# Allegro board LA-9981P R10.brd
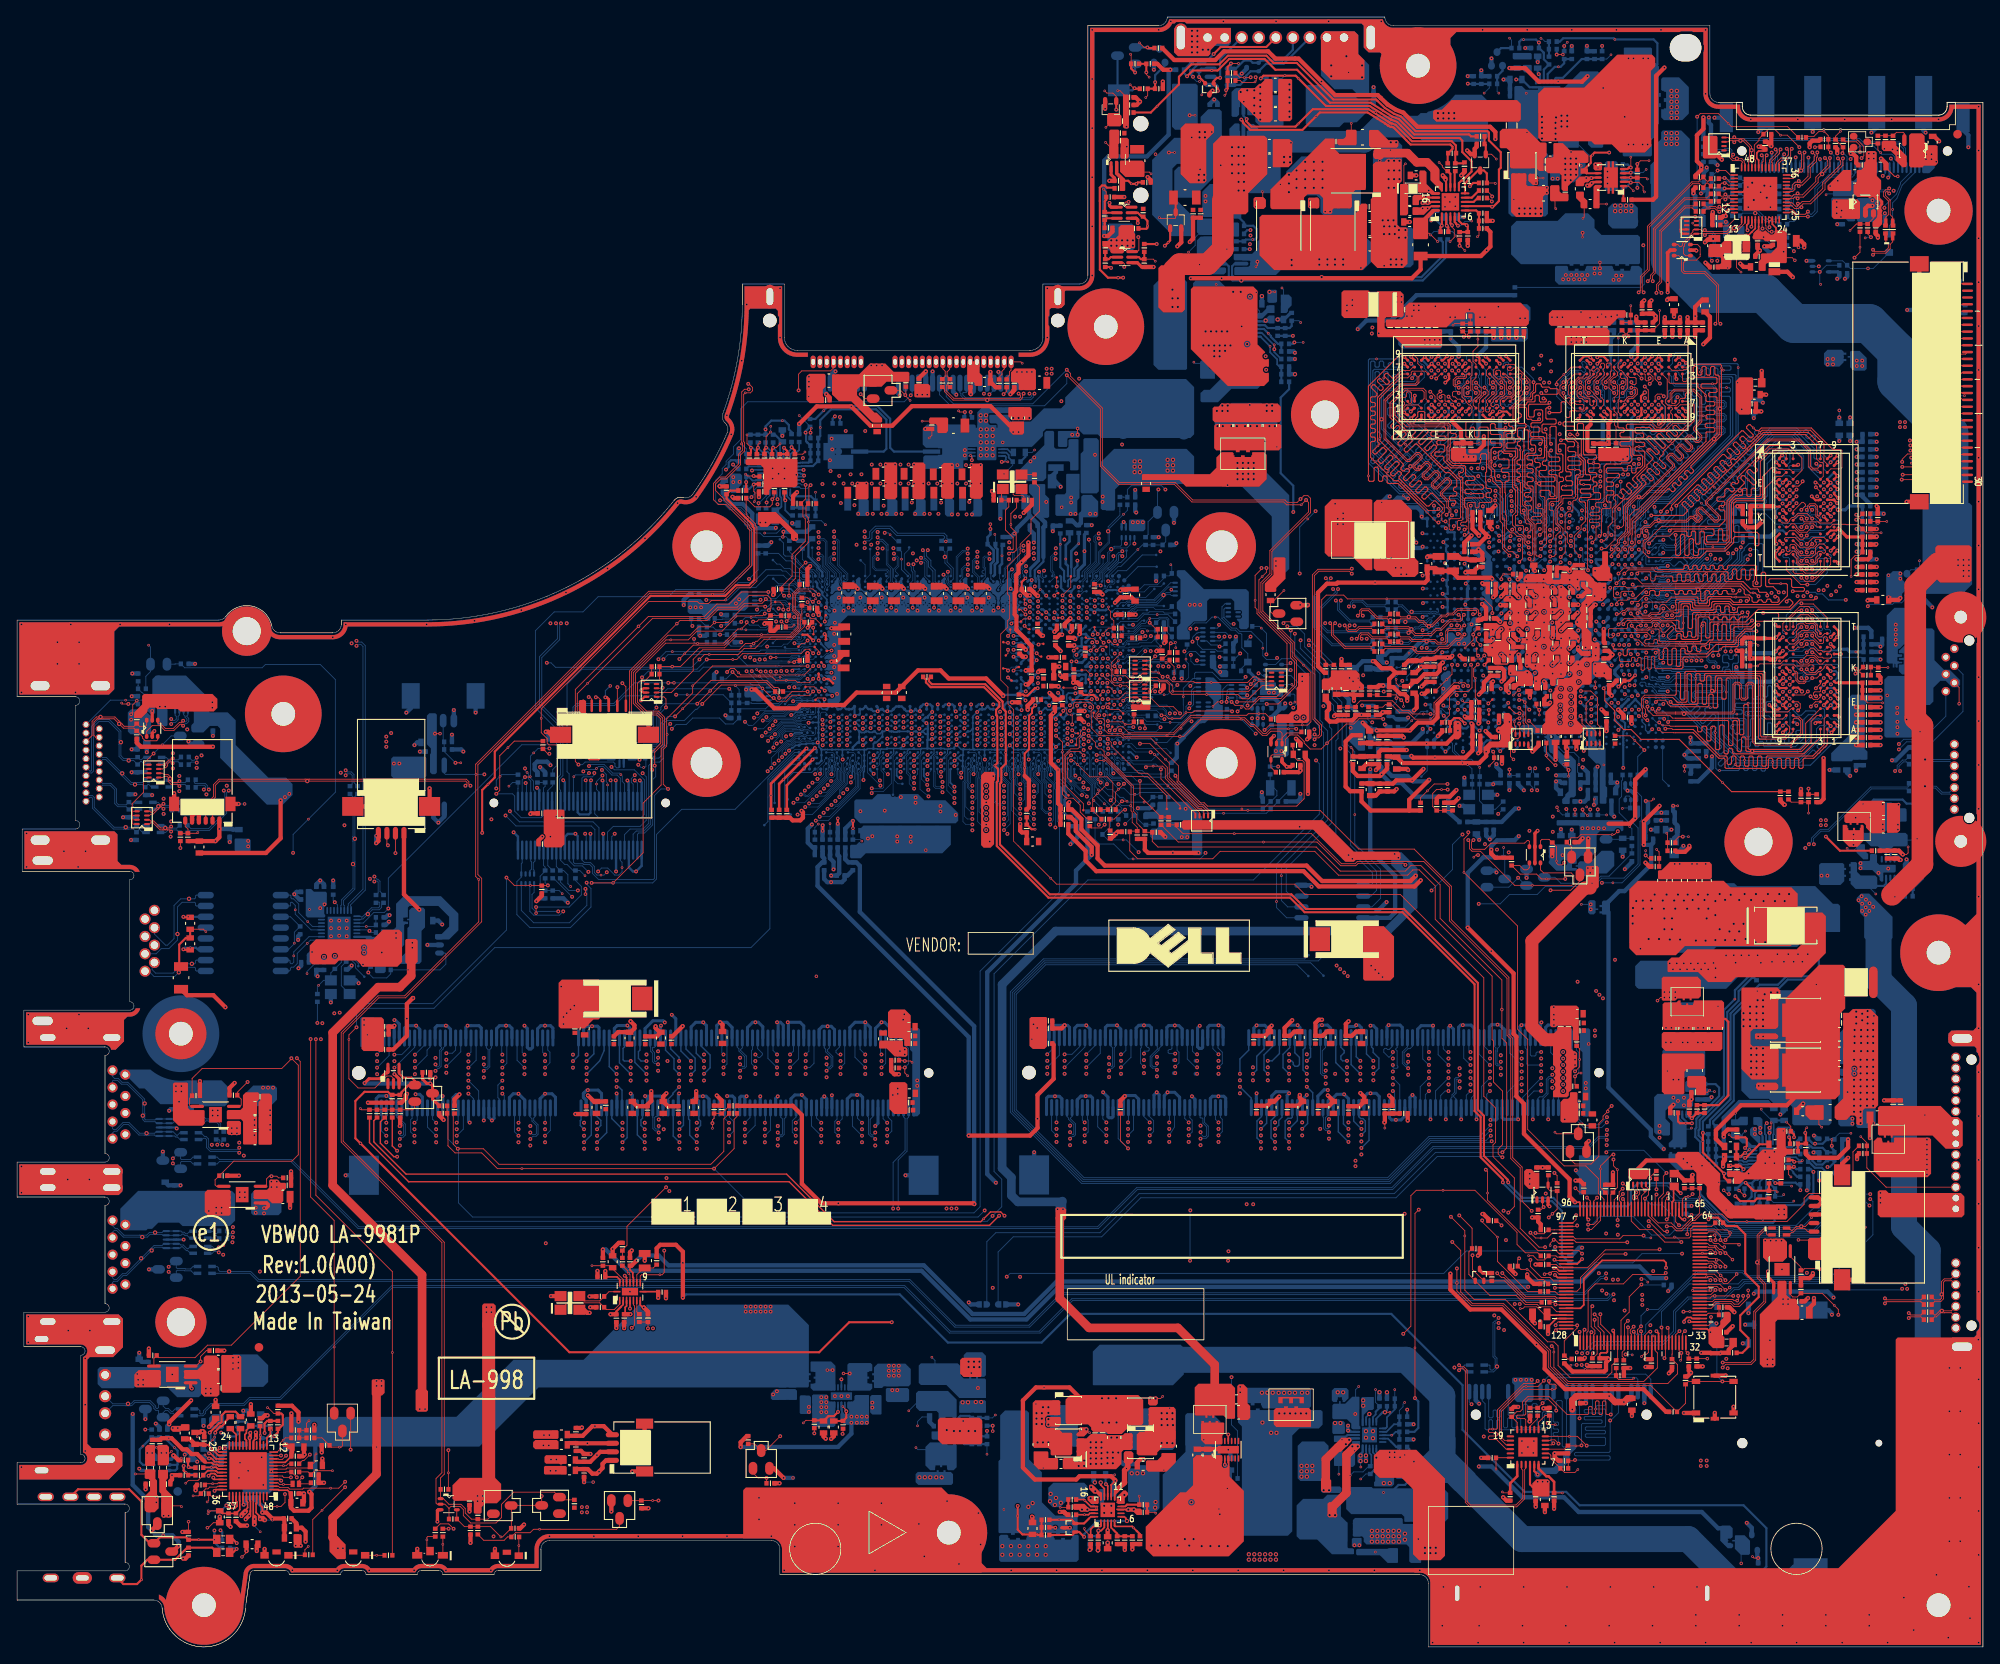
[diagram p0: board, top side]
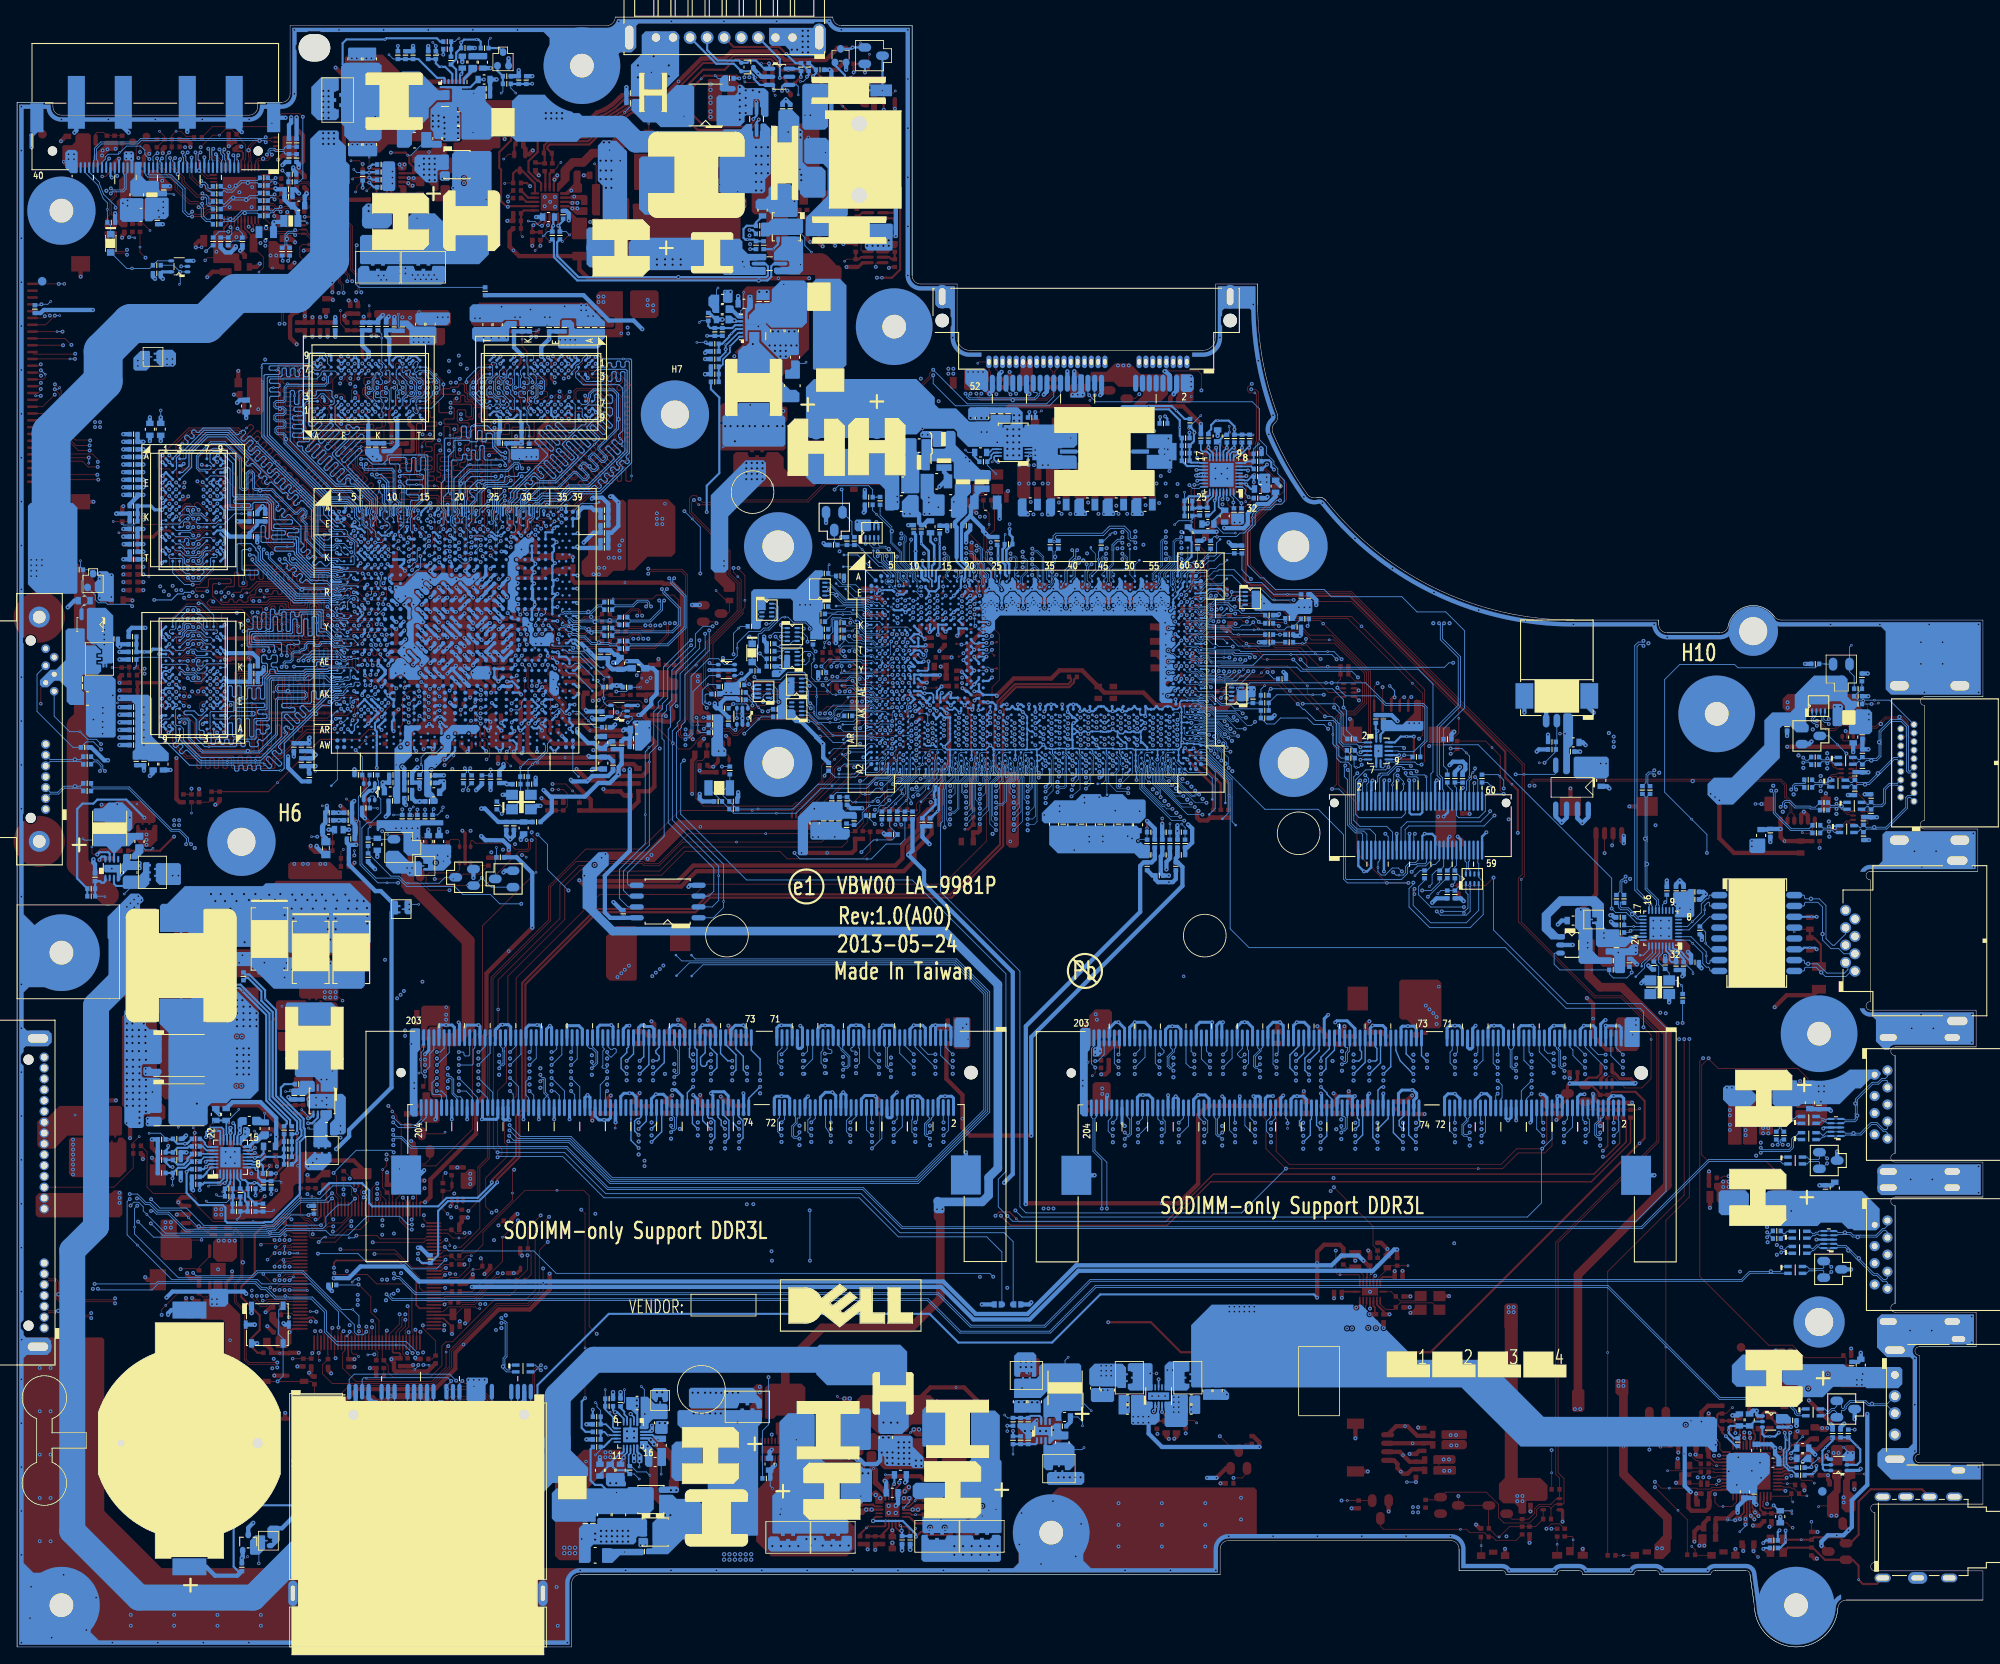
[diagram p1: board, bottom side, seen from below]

Outline 230.4 x 191.1 mm; copper layers: TOP, GND1, IN1, VCC, IN2, IN3, GND2, BOTTOM. Coordinates in mm from the lower left corner of the outline.

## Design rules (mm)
net group CLK_: nets CLK_CPU_ITP CLK_CPU_ITP#
net group CLKA0: nets CLKA0 CLKA0#
net group CLKA1: nets CLKA1 CLKA1#
net group CLKB0: nets CLKB0 CLKB0#
net group CLKB1: nets CLKB1 CLKB1#
net group CSI: nets CSIN CSIP
net group DIFFPAIR2: nets I2C1_SCL_TCH_PAD I2C1_SDA_TCH_PAD
net group DIFFPAIR3: nets CSCL CSDA
net group DIFFPAIR5: nets EC_SMB_CK2 EC_SMB_DA2
net group DIFFPAIR6: nets CPU_DPB_CTRLCLK_R CPU_DPB_CTRLDAT_R
net group DIFFPAIR9: nets CPU_EDP_AUX#_C CPU_EDP_AUX_C
net group DIFFPAIR13: nets QSA3 QSA#3
net group DIFFPAIR14: nets QSA5 QSA#5
net group DIFFPAIR15: nets QSB2 QSB#2
net group DIFFPAIR16: nets QSB4 QSB#4
net group DIFFPAIR17: nets QSA1 QSA#1
net group DIFFPAIR18: nets QSB1 QSB#1
net group DIFFPAIR19: nets QSB5 QSB#5
net group DIFFPAIR20: nets QSA7 QSA#7
net group DIFFPAIR21: nets QSA2 QSA#2
net group DIFFPAIR22: nets QSA4 QSA#4
net group DIFFPAIR23: nets QSB3 QSB#3
net group DIFFPAIR24: nets QSB6 QSB#6
net group DIFFPAIR25: nets QSA0 QSA#0
net group DIFFPAIR26: nets QSB0 QSB#0
net group DIFFPAIR27: nets QSB7 QSB#7
net group DIFFPAIR28: nets QSA6 QSA#6
net group EDID_CLK: nets EDID_CLK EDID_DATA
net group MIIC_SCL: nets MIIC_SCL MIIC_SDA
net group PCIE_PRX_LANTX_P3_C: nets PCIE_PRX_LANTX_N3_C PCIE_PRX_LANTX_P3_C
net group PECI-SINGLE: nets PECI_EC PECI_KB9012
net group SENSE: nets VCCSENSE VSSSENSE
net group SMB-15: nets SML1_SMBCLK SML1_SMBDATA
net group VCIN0_PH: nets ECAGND VCIN0_PH
net group 12: nets PCH_OPI_COMP PCH_PCIE_RCOMP SATA_IREF
net group ASYNC: nets DDR3_DRAMRST# DDR3_DRAMRST#_CPU H_PROCHOT# H_PROCHOT#_R H_VCCST_PWRGD_XDP XDP_OBS0_R XDP_OBS1_R
net group AUDIO: nets PCH_AZ_BITCLK PCH_AZ_CODEC_BITCLK PCH_AZ_CODEC_RST# PCH_AZ_CODEC_SDIN0 PCH_AZ_CODEC_SDOUT PCH_AZ_CODEC_SYNC PCH_AZ_RST# PCH_AZ_SDOUT PCH_AZ_SYNC
net group CLK: nets SUSCLK
net group CLK-SINGLE: nets CLK_PCI_LPC
net group CR_LOW: nets DSWODVREN INTRUDER# PCH_DPWROK PCH_INTVRMEN PCH_RSMRST#_R SYS_PWROK SYS_PWROK_R SYS_RESET#
net group DDRA-ADD: nets DDR_A_BS0 DDR_A_BS1 DDR_A_BS2 DDR_A_CAS# DDR_A_MA0 DDR_A_MA1 DDR_A_MA2 DDR_A_MA3 DDR_A_MA4 DDR_A_MA5 DDR_A_MA6 DDR_A_MA7 DDR_A_MA8 DDR_A_MA9 DDR_A_MA10 DDR_A_MA11 DDR_A_MA12 DDR_A_MA13 DDR_A_MA14 DDR_A_MA15 DDR_A_RAS# DDR_A_WE#
net group DDRA-CTL: nets DDR_CKE0_DIMMA DDR_CKE1_DIMMA DDR_CS0_DIMMA# DDR_CS1_DIMMA# M_ODT0 M_ODT1
net group DDRA-D0: nets DDR_A_D0 DDR_A_D1 DDR_A_D2 DDR_A_D3 DDR_A_D4 DDR_A_D5 DDR_A_D6 DDR_A_D7
net group DDRA-D1: nets DDR_A_D8 DDR_A_D9 DDR_A_D10 DDR_A_D11 DDR_A_D12 DDR_A_D13 DDR_A_D14 DDR_A_D15 DDR_A_DQS1 DDR_A_DQS#1
net group DDRA-D2: nets DDR_A_D16 DDR_A_D17 DDR_A_D18 DDR_A_D19 DDR_A_D20 DDR_A_D21 DDR_A_D22 DDR_A_D23
net group DDRA-D3: nets DDR_A_D24 DDR_A_D25 DDR_A_D26 DDR_A_D27 DDR_A_D28 DDR_A_D29 DDR_A_D30 DDR_A_D31
net group DDRA-D4: nets DDR_A_D32 DDR_A_D33 DDR_A_D34 DDR_A_D35 DDR_A_D36 DDR_A_D37 DDR_A_D38 DDR_A_D39
net group DDRA-D5: nets DDR_A_D40 DDR_A_D41 DDR_A_D42 DDR_A_D43 DDR_A_D44 DDR_A_D45 DDR_A_D46 DDR_A_D47
net group DDRA-D6: nets DDR_A_D48 DDR_A_D49 DDR_A_D50 DDR_A_D51 DDR_A_D52 DDR_A_D53 DDR_A_D54 DDR_A_D55
net group DDRA-D7: nets DDR_A_D56 DDR_A_D57 DDR_A_D58 DDR_A_D59 DDR_A_D60 DDR_A_D61 DDR_A_D62 DDR_A_D63
net group DDRB-ADD: nets DDR_B_BS0 DDR_B_BS1 DDR_B_BS2 DDR_B_CAS# DDR_B_MA0 DDR_B_MA1 DDR_B_MA2 DDR_B_MA3 DDR_B_MA4 DDR_B_MA5 DDR_B_MA6 DDR_B_MA7 DDR_B_MA8 DDR_B_MA9 DDR_B_MA10 DDR_B_MA11 DDR_B_MA12 DDR_B_MA13 DDR_B_MA14 DDR_B_MA15 DDR_B_RAS# DDR_B_WE#
net group DDRB-CTL: nets DDR_CKE2_DIMMB DDR_CKE3_DIMMB DDR_CS2_DIMMB# DDR_CS3_DIMMB# M_ODT2 M_ODT3
net group DDRB-D0: nets DDR_B_D0 DDR_B_D1 DDR_B_D2 DDR_B_D3 DDR_B_D4 DDR_B_D5 DDR_B_D6 DDR_B_D7
net group DDRB-D1: nets DDR_B_D8 DDR_B_D9 DDR_B_D10 DDR_B_D11 DDR_B_D12 DDR_B_D13 DDR_B_D14 DDR_B_D15
net group DDRB-D2: nets DDR_B_D16 DDR_B_D17 DDR_B_D18 DDR_B_D19 DDR_B_D20 DDR_B_D21 DDR_B_D22 DDR_B_D23
net group DDRB-D3: nets DDR_B_D24 DDR_B_D25 DDR_B_D26 DDR_B_D27 DDR_B_D28 DDR_B_D29 DDR_B_D30 DDR_B_D31
net group DDRB-D4: nets DDR_B_D32 DDR_B_D33 DDR_B_D34 DDR_B_D35 DDR_B_D36 DDR_B_D37 DDR_B_D38 DDR_B_D39
net group DDRB-D5: nets DDR_B_D40 DDR_B_D41 DDR_B_D42 DDR_B_D43 DDR_B_D44 DDR_B_D45 DDR_B_D46 DDR_B_D47
net group DDRB-D6: nets DDR_B_D48 DDR_B_D49 DDR_B_D50 DDR_B_D51 DDR_B_D52 DDR_B_D53 DDR_B_D54 DDR_B_D55
net group DDRB-D7: nets DDR_B_D56 DDR_B_D57 DDR_B_D58 DDR_B_D59 DDR_B_D60 DDR_B_D61 DDR_B_D62 DDR_B_D63
net group DP: nets CPU_DPB_AUX CPU_DPB_AUX# CPU_DPC_AUX CPU_DPC_AUX#
net group EDP: nets CPU_EDP_N0_C CPU_EDP_N1_C CPU_EDP_P0_C CPU_EDP_P1_C
net group HDA: nets AUD_HP_OUT_L_CN AUD_HP_OUT_R_CN HPOUT-L HPOUT-R MIC_IN MIC_IN_R RING2 RING2_R
net group HDMI: nets TMDS_L_TX0N TMDS_L_TX0P TMDS_L_TX1N TMDS_L_TX1P TMDS_L_TX2N TMDS_L_TX2P TMDS_L_TXCN TMDS_L_TXCP TMDS_TX0N TMDS_TX0P TMDS_TX1N TMDS_TX1P TMDS_TX2N TMDS_TX2P TMDS_TXCN TMDS_TXCP
net group KB: nets KSI0 KSI1 KSI2 KSI3 KSI4 KSI5 KSI6 KSI7 KSO0 KSO1 KSO2 KSO3 KSO4 KSO5 KSO6 KSO7 KSO8 KSO9 KSO10 KSO11 KSO12 KSO13 KSO14 KSO15 KSO16
net group LPC: nets LPC_LAD0 LPC_LAD1 LPC_LAD2 LPC_LAD3 LPC_LFRAME#
net group LVDS: nets EDP_AUX EDP_AUX# EDP_N0 EDP_N1 EDP_P0 EDP_P1 LVDS_A0+ LVDS_A0- LVDS_A1+ LVDS_A1- LVDS_A2+ LVDS_A2- LVDS_ACLK+ LVDS_ACLK- LVDS_B0+ LVDS_B0- LVDS_B1+ LVDS_B1- LVDS_B2+ LVDS_B2- LVDS_BCLK+ LVDS_BCLK-
net group PCIE: nets PCIE_PRX_LANTX_N3 PCIE_PRX_LANTX_P3 PCIE_PTX_LANRX_N3 PCIE_PTX_LANRX_P3 PCIE_PTX_WLANRX_N4_C PCIE_PTX_WLANRX_P4_C
net group PEG: nets PEG_CTX_GRX_N0 PEG_CTX_GRX_N1 PEG_CTX_GRX_N2 PEG_CTX_GRX_N3 PEG_CTX_GRX_P0 PEG_CTX_GRX_P1 PEG_CTX_GRX_P2 PEG_CTX_GRX_P3
net group POWER: nets +0.675VSP +1.5VS +1.5VSP +1.5VSP_ON +1.35VP +1.35VS_VGA +3V_WLAN +3VALW_PCH +3VALWP +3VLP +3VS_CAM +5V_HDD +5V_PVDD +5V_USB_PWR1 +5V_USB_PWR2 +5V_USB_PWR3 +5V_USB_PWR4 +5VA +5VALWP +5VS_ODD +5VS_TOUCH +AVCC33 +DIMM1_VREF_DQ +DIMM2_VREF_DQ +EC_VCCA +FAN_POWER +INV_PWR_SRC +LAN_IO +LAN_VDD +LCDVDD +MIC2-VREFO +PCH_VCCDSW +PCH_VCCDSW_R +RTCBATT +RTCVCC +SM_VREF_CA +SM_VREF_CA_DIMM +SM_VREF_DQ0 +SM_VREF_DQ0_DIMM1 +SM_VREF_DQ1 +SM_VREF_DQ1_DIMM2 +SW_LX +V18R +VCC_3IN1 +VCC_PWR_SRC +VCCIO_OUT +VCCIOA_OUT +VCHGR +VDISPLAY_VCC
net group RCOMP: nets SM_RCOMP0 SM_RCOMP1 SM_RCOMP2
net group RTC: nets PCH_RTCRST# PCH_RTCX1 PCH_RTCX2 SRTCRST#
net group SATA: nets SATA_PRX_DTX_N0 SATA_PRX_DTX_N0_C SATA_PRX_DTX_N1 SATA_PRX_DTX_P0 SATA_PRX_DTX_P0_C SATA_PRX_DTX_P1 SATA_PTX_DRX_N0 SATA_PTX_DRX_N1 SATA_PTX_DRX_P0 SATA_PTX_DRX_P1
net group SMB_10: nets DDR_XDP_SMBCLK_R1 DDR_XDP_SMBDAT_R1 SML0CLK SML0DATA
net group SPI: nets PCH_SPI_CLK PCH_SPI_CLK_R PCH_SPI_CS0# PCH_SPI_HOLD1# PCH_SPI_HOLD# PCH_SPI_MISO PCH_SPI_MISO_1 PCH_SPI_MOSI PCH_SPI_MOSI_1 PCH_SPI_WP1# PCH_SPI_WP#
net group SPK: nets INT-SPK-L+ INT-SPK-L- INT-SPK-R+ INT-SPK-R-
net group SVID: nets H_CPU_SVIDALRT# H_CPU_SVIDCLK H_CPU_SVIDDATA VR_SVID_ALRT# VR_SVID_CLK VR_SVID_DAT
net group THERMTRIP-SINGLE: nets H_THERMTRIP#
net group USB20: nets USB20_CAM_N7_R USB20_CAM_P7_R USB20_CR_N6_R USB20_CR_P6_R USB20_JUSB3_N2 USB20_JUSB3_N2_R USB20_JUSB3_P2 USB20_JUSB3_P2_R USB20_USBDB_N3_R USB20_USBDB_P3_R
net group USB30: nets USB3RN1_JUSB2 USB3RN1_JUSB2_R USB3RN2_JUSB1 USB3RN2_JUSB1_R USB3RP1_JUSB2 USB3RP1_JUSB2_R USB3RP2_JUSB1 USB3RP2_JUSB1_R USB3TN1_JUSB2_C USB3TN1_JUSB2_R USB3TN2_JUSB1_C USB3TN2_JUSB1_R USB3TP1_JUSB2_C USB3TP1_JUSB2_R USB3TP2_JUSB1_C USB3TP2_JUSB1_R
net group VRAMA-ADD: nets CASA0# CASA1# CKEA0 CKEA1 CSA0#_0 CSA1#_0 RASA0# RASA1# WEA0# WEA1#
net group VRAMB-ADD: nets CASB0# CASB1# CKEB0 CKEB1 CSB0#_0 CSB1#_0 DRAM_RST# DRAM_RST#_R RASB0# RASB1# WEB0# WEB1#
nets with their own width: min track width 0.254; nets +1.8VSP +3VALW +VGA_CORE +VGA_PCIEP CLK_BIASREF
nets with their own width: min track width 0.508; nets +0.675VS +1.2VSP_B+ +1.05V_PGOOD +1.05VS_APLLOPI +1.05VS_ASATA3PLL +1.05VS_AUSB3PLL +1.05VS_AXCK_DCB +1.05VS_AXCK_LCPLL +1.05VSP +1.8VGS +1.8VS +1.8VSP_ON +1.35V +1.35V_MEM_GFX +1.35VGPUP +3VALW_PCH_GATE +3VGS +3VS +3VS_RT +5VALW +5VS +AVDD +BIF_VDDC +CHGRTC +CPU_CORE +DPAB_VDD10 +DPAB_VDD18 +DPCD_VDD10 +DPCD_VDD18 +DPEF_VDD10 +DPEF_VDD18 +DPLL_PVDD +DPLL_VDDC +LCDVDD_CONN +MPV18 +PCIE_PVDD +PCIE_VDDR +SPV10 +SPV18 +TSVDD +VCCIO_OUT_R +VCCRTCEXT +VDD1DI +VDD_MEM15_REFDA +VDD_MEM15_REFDB +VDD_MEM15_REFSA +VDD_MEM15_REFSB +VDDC_CT +VDDCI +VDDCIP +VDDR4 +VREFG_GPU EDP_COMP GND GNDA
nets with their own width: min track width 1.016; nets +DVCC33
nets with their own width: min track width 1.27; nets +1.05VS
nets with their own width: min track width 1.524; nets +SWR_V12

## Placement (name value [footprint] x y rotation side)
C35  -  [C_0402]  107.79 96.92 270 bottom
C36  -  [C_0402]  105.63 96.92 270 bottom
C37  -  [C_0402]  103.47 96.92 270 bottom
C38  -  [C_0402]  101.31 96.92 270 bottom
C39  -  [C_0603]  108.87 97.17 270 bottom
C40  -  [C_0603]  101.92 112.61 270 top
C41  -  [C_0603]  106.71 97.1 270 bottom
C42  -  [C_0603]  104.55 97.1 270 bottom
C43  -  [C_0603]  103.69 112.61 270 top
C44  -  [C_0603]  132.32 137.13 270 top
C45  -  [C_0603]  102.39 97.1 270 bottom
C50  -  [C_0402]  123.22 118.32 270 top
C51  -  [C_0402]  149.5 105.74 0 top
C52  -  [C_0402]  124.68 111.95 90 top
C53  -  [C_0402]  124.55 119.68 180 top
C54  -  [C_0402]  134.08 97.31 270 bottom
C55  -  [C_0402]  134.97 97.31 270 bottom
C56  -  [C_0402]  135.86 97.31 270 bottom
C57  -  [C_0402]  130.34 121.04 180 top
C58  -  [C_0402]  120.48 131.46 0 bottom
C59  -  [C_1206]  119.66 134.19 0 bottom
C60  -  [C_0603]  131.03 122.63 90 top
C61  -  [C_0402]  122.79 119.71 180 top
C62  -  [C_0402]  129.95 123.06 90 top
C63  -  [C_0402]  125.31 130.62 90 bottom
C64  -  [C_0402]  118.33 96.42 270 top
C65  -  [C_1206]  125.44 134.06 0 bottom
C66  -  [C_0603]  119.73 94.44 180 top
C67  -  [C_0402]  119.99 111.07 180 top
C68  -  [C_0402]  123.85 114.64 270 top
C69  -  [C_0402]  118.9 114.51 270 top
C70  -  [C_1206]  125.3 136.26 0 bottom
C71  -  [C_0402]  121.69 118.39 270 top
C72  -  [C_0603]  100.23 97.1 270 bottom
C73  -  [C_0402]  122.72 116.03 180 top
C74  -  [C_0603]  99.03 97.1 270 bottom
C75  -  [C_0402]  117.43 110.75 90 top
C76  -  [C_0402]  120.29 112.66 0 top
C77  -  [C_0402]  121.63 110.17 90 top
C78  -  [C_0603]  122.9 113.74 180 top
C79  -  [C_0402]  91.71 124.57 0 top
C80  -  [C_0402]  92.27 120.15 0 top
C81  -  [C_0402]  124.46 109.75 270 top
C82  -  [C_0603]  122.9 114.95 180 top
C83  -  [C_0402]  119.6 119.97 270 top
C84  -  [C_1206]  121.3 136.66 0 bottom
C85  -  [C_0402]  119.61 131.46 180 bottom
C86  -  [C_1206]  118.2 134.19 180 bottom
C87  -  [C_0402]  120.3 113.54 90 top
C88  -  [C_0402]  117.5 117.37 270 top
C2305  -  [C_0603]  99.53 29.03 0 bottom
C2306  -  [C_0603]  99.53 27.82 0 bottom
C2307  -  [C_0805]  102.58 30.96 270 bottom
C2308  -  [C_0603]  104.04 31.06 270 bottom
C2309  -  [C_0603]  95.72 26.49 270 top
C2310  -  [C_0805]  142.31 27.51 0 top
C2311  -  [C_0603]  138.33 21.79 90 top
C2312  -  [C_0603]  142.21 29.03 0 top
C2313  -  [C_0603]  139.54 21.79 90 top
C2314  -  [C_0603]  142.21 20.74 90 bottom
C2316  -  [C_0603]  93.5 27.82 180 bottom
C2318  -  [C_0603]  93.5 29.03 180 bottom
C2322  -  [C_0603]  94.52 26.49 270 top
C2323  -  [C_0603]  89.69 30.74 270 bottom
C2324  -  [C_0603]  90.9 30.74 270 bottom
C2326  -  [C_0402]  142.55 114.97 180 bottom
C2327  -  [C_0402]  159.36 85.48 90 bottom
C5212  -  [C_0402]  83.2 117.8 0 bottom
CA1  -  [C_0603]  28.54 25.92 90 bottom
CA2  -  [C_0603]  27.33 25.92 90 bottom
CA21  -  [C_0402]  34.43 20.2 0 top
CA22  -  [C_0402]  34.43 19.25 0 top
CA23  -  [C_0603]  20.41 22.11 0 bottom
CA24  -  [C_0402]  22.46 17.98 180 top
CA25  -  [C_0402]  21.1 19 0 top
CA29  -  [C_0402]  65.5 24.76 90 top
CA30  -  [C_0402]  65.5 23.9 270 top
CA31  -  [C_0402]  66.45 21.71 90 top
CA32  -  [C_0402]  66.45 20.85 270 top
CA33  -  [C_0402]  20.09 12.57 90 top
CA38  -  [C_0402]  15.98 19.12 180 top
CA39  -  [C_0402]  20.09 11.64 270 top
CA40  -  [C_0402]  17.05 19.09 0 top
CA51  -  [C_0402]  21.94 23.68 90 top
CA53  -  [C_0603]  27.91 17.47 90 bottom
CA54  -  [C_0402]  26.83 17.46 90 bottom
CA55  -  [C_0603]  31.33 13.98 0 top
CA56  -  [C_0402]  31.26 15.06 0 top
CA57  -  [C_0603]  32.1 16.9 0 top
CA58  -  [C_0402]  32.08 17.98 0 top
CA59  -  [C_0603]  32.22 23.44 0 top
CA60  -  [C_0402]  32.15 22.36 0 top
CA61  -  [C_0603]  23.75 15.96 270 top
CA62  -  [C_0603]  20.41 23.32 0 bottom
CA63  -  [C_0603]  23.75 14.56 90 bottom
CA64  -  [C_0603]  35.78 21.28 180 top
CA65  -  [C_0402]  32.15 24.52 0 top
CA67  -  [C_0603]  24.98 25.6 90 top
CA68  -  [C_0603]  26.19 25.6 90 top
CA69  -  [C_0402]  33.06 25.41 180 top
CA71  -  [C_0603]  20.86 23.76 90 top
CA74  -  [C_0603]  27.4 25.92 90 top
CC1  -  [C_0402]  146 99.13 0 bottom
CC2  -  [C_0402]  148.7 99.13 180 bottom
CC3  -  [C_0402]  129.49 95.58 0 top
CC4  -  [C_0402]  133.96 95.51 180 top
CC5  -  [C_0402]  127.21 95.26 0 bottom
CC6  -  [C_0402]  118.92 134.46 180 top
CC7  -  [C_0402]  114.45 134.46 0 top
CC8  -  [C_0402]  97.05 95.53 0 bottom
CC9  -  [C_0402]  94.41 95.53 180 bottom
CC10  -  [C_0402]  96.19 95.53 180 bottom
CC11  -  [C_0402]  149.5 103.39 0 top
CC13  -  [C_0402]  70.27 108.34 90 bottom
CC14  -  [C_0402]  61.95 97.74 180 top
CC15  -  [C_0402]  62.03 94.13 180 top
CC16  -  [C_0402]  61.89 88.68 270 bottom
CC17  -  [C_0402]  61.89 101.36 90 bottom
CC18  -  [C_0402]  158.88 117.94 0 bottom
CC19  -  [C_0402]  158.88 117.05 0 bottom
CC20  -  [C_0402]  160.66 119.46 0 bottom
CC21  -  [C_0402]  160.66 118.57 0 bottom
CC22  -  [C_0402]  158.88 120.73 0 bottom
CC23  -  [C_0402]  158.88 119.84 0 bottom
CC24  -  [C_0402]  160.66 122.51 0 bottom
CC25  -  [C_0402]  160.66 121.62 0 bottom
CC26  -  [C_0603]  136.93 97.29 270 bottom
CC27  -  [C_0402]  86.85 128.22 90 bottom
CC28  -  [C_0402]  79.02 122.5 90 bottom
CC29  -  [C_0402]  71.16 108.34 90 bottom
CC30  -  [C_0402]  63.21 106.42 180 bottom
CC31  -  [C_0402]  61.5 89.27 270 top
CC32  -  [C_0402]  39.91 100.01 90 bottom
CC33  -  [C_0402]  150.52 107.29 0 top
CC34  -  [C_0402]  133.45 112.7 0 top
CC35  -  [C_0402]  50.4 62.56 180 top
CC40  -  [C_0402]  39.02 100.01 90 bottom
CD1  -  [C_0402]  42.62 71.83 0 top
CD2  -  [C_0402]  42.62 72.72 0 top
CD3  -  [C_0402]  51.27 62.55 90 top
CD4  -  [C_0402]  73.88 62.48 90 top
CD5  -  [C_0402]  68.99 63.05 90 top
CD6  -  [C_0402]  66.7 63.4 270 top
CD7  -  [C_0402]  65.37 72.01 90 top
CD8  -  [C_0402]  69.94 70.67 90 top
CD9  -  [C_0402]  77.5 62.48 90 top
CD10  -  [C_0402]  76.7 70.69 90 top
CD11  -  [C_0402]  73.63 70.67 90 top
CD12  -  [C_0603]  75.72 62.56 90 top
CD13  -  [C_0603]  75.47 70.69 90 top
CD14  -  [C_0603]  82.68 70.76 90 top
CD15  -  [C_D3]  73.27 76.02 180 top
CD16  -  [C_0603]  67.91 62.56 90 top
CD17  -  [C_0603]  72.1 62.56 90 top
CD18  -  [C_0603]  79.34 62.56 90 top
CD19  -  [C_0603]  66.51 71.77 90 top
CD20  -  [C_0603]  71.78 70.69 90 top
CD21  -  [C_0402]  81.69 62.55 90 top
CD22  -  [C_0402]  82.58 62.55 90 top
CD23  -  [C_0402]  47.51 67.36 0 top
CD24  -  [C_0402]  105.26 70.75 180 top
CD25  -  [C_0402]  105.26 71.64 180 top
CD26  -  [C_0402]  105.01 62.94 180 top
CD27  -  [C_0402]  104.94 63.83 180 top
CD28  -  [C_0603]  105.29 64.91 180 top
CD29  -  [C_0603]  105.25 72.72 180 top
CD30  -  [C_0402]  102.58 70.74 90 top
CD31  -  [C_0402]  103.47 70.74 90 top
CD32  -  [C_0402]  120.41 73.42 0 top
CD33  -  [C_0402]  120.41 72.53 0 top
CD34  -  [C_0402]  129.31 62.55 90 top
CD35  -  [C_0402]  152.49 62.55 90 top
CD36  -  [C_0402]  148.87 62.55 90 top
CD37  -  [C_0402]  145.25 62.55 90 top
CD38  -  [C_0402]  156.05 62.48 90 top
CD39  -  [C_0402]  155.73 70.74 90 top
CD40  -  [C_0402]  152.17 70.74 90 top
CD41  -  [C_0402]  148.56 70.74 90 top
CD42  -  [C_0402]  144.94 70.74 90 top
CD43  -  [C_0603]  150.65 62.56 90 top
CD44  -  [C_0603]  147.03 62.56 90 top
CD45  -  [C_0603]  154.27 62.56 90 top
CD46  -  [C_0603]  146.78 70.75 90 top
CD47  -  [C_0603]  150.33 70.75 90 top
CD48  -  [C_0603]  153.95 70.75 90 top
CD49  -  [C_0603]  157.57 70.75 90 top
CD50  -  [C_0603]  157.89 62.56 90 top
CD51  -  [C_D3]  152.68 82.98 0 top
CD52  -  [C_0402]  160.3 62.55 90 top
CD53  -  [C_0402]  161.19 62.55 90 top
CD54  -  [C_0402]  183.62 72.27 180 top
CD55  -  [C_0402]  183.62 73.16 180 top
CD56  -  [C_0402]  183.56 62.56 180 top
CD57  -  [C_0402]  183.56 63.45 180 top
CD58  -  [C_0603]  183.83 64.53 180 top
CD59  -  [C_0603]  183.54 74.24 180 top
CD60  -  [C_0402]  180.94 72.26 90 top
CD61  -  [C_0402]  181.83 72.26 90 top
CD62  -  [C_0603]  101.5 70.58 90 top
CD63  -  [C_0402]  53.03 17.56 270 top
CD64  -  [C_0402]  44.9 62.98 270 top
CE1  -  [C_0402]  199.41 36.9 0 top
CE2  -  [C_0402]  191.54 33.74 270 top
CE5  -  [C_0402]  178.51 37.54 0 top
CE6  -  [C_0402]  185.49 32.93 90 top
CE7  -  [C_0402]  200.61 34.49 0 top
CE8  -  [C_0402]  196.31 53.78 90 top
CE9  -  [C_0402]  199.94 49.73 180 top
CE11  -  [C_0402]  199.47 39.83 0 top
CE12  -  [C_0402]  187.4 31.82 0 top
CE15  -  [C_0402]  178.08 55.31 90 top
CE16  -  [C_0805]  179.31 39 180 top
CE18  -  [C_0402]  178.58 44.84 0 top
CE19  -  [C_0402]  179.48 55.31 90 top
CE20  -  [C_0402]  195.55 30.8 90 top
CE22  -  [C_0603]  48.73 106.06 180 bottom
CE23  -  [C_0402]  48.81 104.98 180 bottom
CE24  -  [C_0402]  50.05 106.12 0 bottom
CE25  -  [C_0603]  44.73 102.31 270 bottom
CE26  -  [C_0402]  183.61 53.34 90 top
CE27  -  [C_0402]  184.62 33.84 270 top
CE28  -  [C_0402]  188.31 33.61 270 top
CE29  -  [C_0402]  193.96 33.74 270 top
CE30  -  [C_0402]  175.87 44.65 180 top
CE31  -  [C_0402]  196.85 33.81 270 top
CE32  -  [C_0402]  173.36 49.97 180 top
CE33  -  [C_0402]  182.2 33.77 0 top
CE34  -  [C_0402]  172.84 42.92 90 top
CE35  -  [C_0402]  170.53 46.71 0 top
CE36  -  [C_0402]  192.99 42.44 0 bottom
CG1  -  [C_0402]  71.83 44.7 90 top
CG2  -  [C_0402]  71.15 39.01 270 top
CG3  -  [C_0402]  75.14 41.6 0 top
CG4  -  [C_0402]  68.94 43.38 180 top
CG5  -  [C_0805]  73.56 44.44 90 top
CG6  -  [C_0603]  69.8 44.46 90 top
CG7  -  [C_0402]  73.94 38.1 90 top
CG8  -  [C_0402]  68.81 39.83 180 top
CG9  -  [C_0402]  68.81 41.1 180 top
CG10  -  [C_0402]  70.23 39 270 top
CG11  -  [C_0402]  70.95 46.47 90 top
CI1  -  [C_MP6VLPS220MC4R2]  22.88 64.34 180 bottom
CI2  -  [C_0402]  19.21 63.97 270 bottom
CI3  -  [C_0402]  23.33 60.41 270 bottom
CI4  -  [C_0402]  24.22 60.41 270 bottom
CI6  -  [C_0805]  30.29 52.78 0 top
CI7  -  [C_0402]  31.19 54.11 0 top
CI8  -  [C_MP6VLPS220MC4R2]  23.58 52.72 180 bottom
CI9  -  [C_0402]  18.44 53.21 90 bottom
CI10  -  [C_0402]  23.7 47.88 0 bottom
CI11  -  [C_0402]  23.7 48.78 0 bottom
CI12  -  [C_0805]  27.04 61.48 0 top
CI13  -  [C_0402]  25.81 64.69 180 top
CI14  -  [C_0402]  28.01 64.53 0 top
CI15  -  [C_0402]  20.51 64.63 0 top
CI16  -  [C_0402]  22.56 34.75 0 top
CI17  -  [C_0402]  23.7 55.26 0 top
CI18  -  [C_0805]  27.03 59.66 0 top
CI19  -  [C_0402]  15.4 32.51 90 bottom
CI20  -  [C_MP6VLPS220MC4R2]  21.68 31.51 180 bottom
CI21  -  [C_0805]  27.04 63.19 0 top
CI22  -  [C_0402]  23.45 30.36 0 top
CI23  -  [C_0805]  22.74 31.7 0 top
CI24  -  [C_0402]  16.36 34.17 180 top
CI25  -  [C_0402]  209.07 41.46 90 top
CI26  -  [C_0402]  31.19 55 0 top
CI27  -  [C_0805]  22.74 33.41 0 top
CI30  -  [C_0402]  208.23 40.52 0 top
CI31  -  [C_0805]  208.35 39.19 0 top
CI32  -  [C_0402]  209.07 44.16 270 top
CI40  -  [C_0603]  20.29 64.53 270 bottom
CI43  -  [C_0603]  17.36 53.1 90 bottom
CI44  -  [C_0603]  14.32 32.33 90 bottom
CL15  -  [C_0402]  34.2 80.27 180 bottom
CL19  -  [C_0402]  42.95 82.45 270 bottom
CL20  -  [C_0402]  35.97 80.29 270 bottom
CL22  -  [C_0402]  34.2 87.64 180 bottom
CL26  -  [C_0402]  34.2 88.53 180 bottom
CL30  -  [C_0402]  42.07 88.16 270 bottom
CL31  -  [C_0402]  42.95 88.16 270 bottom
CL33  -  [C_1206]  19.22 79.78 270 top
CL34  -  [C_0402]  35.97 88.2 90 bottom
CL35  -  [C_0402]  35.08 88.2 90 bottom
CL36  -  [C_0402]  37.24 80.41 270 bottom
CL37  -  [C_0402]  38.57 79.44 90 bottom
CL38  -  [C_0603]  47.32 85.16 0 bottom
CL39  -  [C_0402]  43.78 80.47 180 bottom
CL41  -  [C_0402]  33.18 83.56 90 bottom
CM40  -  [C_0402]  94.31 146.19 0 top
CM43  -  [C_0603]  112.68 148.32 0 top
CM44  -  [C_0402]  109.33 147.73 90 top
CM45  -  [C_0603]  100.8 143.89 270 top
CM46  -  [C_0402]  116.87 147.7 90 top
CM47  -  [C_0402]  105.69 147.76 90 top
CM48  -  [C_0402]  111.73 147.74 90 top
CM49  -  [C_0402]  108.45 147.73 90 top
CMOS1  -  [SHORTPADS]  113.18 40.16 0 bottom
CR1  -  [C_0402]  177.98 18.06 270 top
CR2  -  [C_0603]  179.06 17.98 270 top
CR3  -  [C_0402]  180.14 17.14 90 top
CR4  -  [C_0402]  172.42 22.17 0 top
CR5  -  [C_0402]  181.79 21.83 180 top
CR6  -  [C_0402]  177.32 28.03 270 top
CR7  -  [C_0402]  182.26 28.59 0 top
CR8  -  [C_0603]  189.26 29.16 270 top
CR9  -  [C_0402]  179.58 27.13 90 top
CR10  -  [C_0402]  181.77 23.61 270 top
CR11  -  [C_0402]  175.16 26.99 90 top
CS5  -  [C_0402]  220.75 63.17 90 top
CS6  -  [C_0402]  219.87 63.17 90 top
CS7  -  [C_0805]  218.86 62.08 180 top
CS8  -  [C_0402]  222.64 100.36 180 bottom
CS9  -  [C_0402]  222.64 101.25 180 bottom
CS10  -  [C_0402]  223.18 113.49 180 bottom
CS11  -  [C_0402]  223.18 112.6 180 bottom
CS12  -  [C_0805]  223 111.2 180 bottom
CS13  -  [C_0402]  219.5 118.18 180 bottom
CS14  -  [C_0402]  222.64 103.5 180 bottom
CS15  -  [C_0402]  222.64 104.39 180 bottom
CS16  -  [C_0603]  221.83 122.68 0 bottom
CS17  -  [C_0402]  222.93 105.47 180 bottom
CS105  -  [C_0402]  224.39 38.36 180 top
CS106  -  [C_0402]  224.39 39.25 180 top
CS108  -  [C_0402]  224.39 41.03 180 top
CS109  -  [C_0402]  224.39 40.14 180 top
CV43  -  [C_0402]  159.08 117.61 0 top
CV44  -  [C_0402]  159.08 116.72 0 top
CV45  -  [C_0402]  160.92 118.76 0 top
CV46  -  [C_0402]  160.92 117.87 0 top
CV47  -  [C_0402]  159.08 119.96 0 top
CV48  -  [C_0402]  159.08 119.07 0 top
CV49  -  [C_0402]  160.92 120.22 0 top
CV50  -  [C_0402]  160.92 121.11 0 top
CV75  -  [C_0402]  166.09 114.06 270 top
CV76  -  [C_0402]  165.2 114.06 270 top
CV77  -  [C_0603]  163.73 113.22 270 top
CV78  -  [C_0402]  165.2 115.84 270 top
CV79  -  [C_0402]  166.09 115.84 270 top
CV80  -  [C_0603]  163.73 115.64 270 top
CV81  -  [C_0402]  185.01 102.24 180 bottom
CV82  -  [C_0603]  161.7 105.35 90 bottom
CV83  -  [C_0402]  170.45 108.97 0 top
CV84  -  [C_0402]  170.45 109.86 0 top
CV86  -  [C_0603]  161.7 104.33 270 bottom
CV87  -  [C_0402]  170.57 105.92 0 top
CV88  -  [C_0402]  170.57 106.81 0 top
CV91  -  [C_0603]  158.52 107.57 180 bottom
CV92  -  [C_0402]  158.6 105.54 180 bottom
CV93  -  [C_0402]  158.6 106.49 180 bottom
CV94  -  [C_0402]  170.54 101.16 180 bottom
CV95  -  [C_0402]  171.4 101.16 0 bottom
CV97  -  [C_0805]  166.59 126.16 90 top
CV101  -  [C_0603]  182.21 93.73 90 bottom
CV102  -  [C_0603]  180.94 93.73 90 bottom
CV103  -  [C_0603]  188.18 94.81 270 bottom
CV108  -  [C_0402]  174.22 106.68 180 top
CV109  -  [C_0402]  174.6 109.16 180 top
CV110  -  [C_0603]  161.7 104.33 270 top
CV111  -  [C_0603]  182.27 100.21 180 bottom
CV112  -  [C_0402]  182.34 101.3 180 bottom
CV113  -  [C_0402]  182.34 102.19 180 bottom
CV114  -  [C_0402]  160.55 105.91 90 top
CV115  -  [C_0402]  159.6 105.91 90 top
CV116  -  [C_0603]  158.52 105.99 90 top
CV117  -  [C_0603]  185.95 100.28 0 bottom
CV118  -  [C_0402]  185.88 102.24 0 bottom
CV119  -  [C_0402]  185.88 101.35 0 bottom
CV120  -  [C_0603]  157.63 104.4 270 top
CV121  -  [C_0402]  159.61 104.43 270 top
CV122  -  [C_0402]  158.72 104.43 270 top
CV123  -  [C_0603]  158.65 101.22 270 top
CV124  -  [C_0402]  160.62 101.22 270 top
CV125  -  [C_0402]  159.73 101.22 270 top
CV126  -  [C_0402]  155.76 112.6 270 top
CV127  -  [C_0402]  156.68 112.54 270 top
CV128  -  [C_0402]  155.22 114.23 90 top
CV129  -  [C_0402]  156.17 114.23 90 top
CV130  -  [C_0402]  157.57 112.54 270 top
CV131  -  [C_0603]  154.65 113.1 270 top
CV132  -  [C_0402]  161.13 115.94 90 bottom
CV133  -  [C_0402]  162.02 115.94 90 bottom
CV134  -  [C_0603]  159.73 114.62 90 bottom
CV135  -  [C_B2]  160.34 157.43 0 top
CV136  -  [C_0603]  197.83 156.53 90 top
CV137  -  [C_0603]  203.55 144.79 90 bottom
CV138  -  [C_0603]  172.61 131.84 90 top
CV139  -  [C_0603]  217.96 122.76 0 top
CV140  -  [C_0603]  194.2 156.67 90 top
CV141  -  [C_0402]  191.35 156.33 90 top
CV142  -  [C_0402]  171.49 132.15 180 top
CV143  -  [C_0402]  170.54 129.29 180 top
CV144  -  [C_0402]  186.27 109.43 270 top
CV145  -  [C_0402]  190.45 156.3 90 top
CV146  -  [C_0402]  172.16 120.6 0 top
CV147  -  [C_0402]  172.37 123.71 0 top
CV148  -  [C_0402]  172.37 124.61 0 top
CV149  -  [C_0402]  171.73 127.53 270 top
CV150  -  [C_0402]  170.54 128.4 180 top
CV151  -  [C_0603]  170.65 127.46 270 top
CV152  -  [C_0402]  162.17 156.78 0 top
CV153  -  [C_0402]  171.49 133.04 180 top
CV154  -  [C_0402]  188.28 108.98 0 top
CV155  -  [C_0402]  188.38 113.29 180 top
CV156  -  [C_0402]  186.08 117.71 270 top
CV170  -  [C_0603]  171.03 96.73 270 bottom
CV171  -  [C_0402]  173.06 96.73 270 bottom
CV172  -  [C_0402]  172.18 96.73 270 bottom
CV173  -  [C_0402]  173.58 114.78 270 top
CV174  -  [C_0402]  172.68 114.78 270 top
CV187  -  [C_0603]  177.19 113.41 270 top
CV188  -  [C_0402]  176.19 113.48 180 top
CV189  -  [C_0402]  175.43 112.59 180 top
CV190  -  [C_0402]  175.28 114.82 0 top
CV193  -  [C_0402]  186.59 113.68 270 top
CV194  -  [C_0402]  185.95 114.99 90 top
CV195  -  [C_0402]  174.52 124.52 0 top
CV196  -  [C_0402]  174.52 123.63 0 top
CV197  -  [C_0603]  202.9 146.83 0 top
CV198  -  [C_0402]  202.88 145.75 0 top
CV199  -  [C_0402]  202.82 144.86 0 top
CV200  -  [C_0603]  190.78 95.83 0 bottom
CV201  -  [C_0402]  191.14 97.81 0 bottom
CV202  -  [C_0402]  191.14 96.92 0 bottom
CV203  -  [C_0402]  183.54 120.7 0 top
CV204  -  [C_0402]  184.25 122.83 90 top
CV205  -  [C_0402]  183.49 119.76 0 top
CV206  -  [C_0402]  183.48 125.93 90 top
CV207  -  [C_0402]  179.54 125.62 0 top
CV208  -  [C_0402]  183.51 121.59 0 top
CV209  -  [C_0402]  184.45 124.61 180 top
CV210  -  [C_0402]  179.57 126.51 0 top
CV211  -  [C_0402]  182.6 125.93 90 top
CV212  -  [C_0402]  181.33 125.55 90 top
CV213  -  [C_0603]  182.75 107.48 270 top
CV214  -  [C_0603]  181.54 107.48 270 top
CV215  -  [C_0603]  194.59 95.83 180 bottom
CV216  -  [C_0402]  194.28 96.92 180 bottom
CV217  -  [C_0402]  194.28 97.81 180 bottom
CV218  -  [C_0402]  194.35 94.3 180 top
CV219  -  [C_0402]  191.53 92.46 0 top
CV220  -  [C_0402]  161.11 128.85 0 bottom
CV221  -  [C_0402]  161.11 133.3 0 bottom
CV222  -  [C_0402]  209.07 99.05 90 top
CV223  -  [C_0402]  196.2 103.27 90 bottom
CV224  -  [C_0402]  196.18 105.95 270 bottom
CV225  -  [C_0402]  170.33 156.04 180 top
CV226  -  [C_0402]  168.61 141.13 270 top
CV227  -  [C_0402]  170.32 154.25 90 bottom
CV228  -  [C_0402]  171.27 141.13 270 bottom
CV229  -  [C_0402]  168.03 154.25 90 bottom
CV230  -  [C_0402]  186.51 141.08 270 top
CV231  -  [C_0402]  189.94 154.37 90 top
CV232  -  [C_0402]  186.18 154.31 90 bottom
CV233  -  [C_0402]  189.24 141.13 270 bottom
CV234  -  [C_0402]  189.13 156.16 180 top
CV235  -  [C_0402]  173.94 154.25 90 top
CV236  -  [C_0402]  184.35 154.31 90 top
CV237  -  [C_0402]  183.46 154.31 90 top
CV238  -  [C_0402]  173.05 154.25 90 top
CV239  -  [C_0402]  193.12 154.37 90 bottom
CV240  -  [C_0402]  189.05 154.37 90 bottom
CV241  -  [C_0402]  189.94 154.37 90 bottom
CV242  -  [C_0402]  164.48 154.25 90 bottom
CV243  -  [C_0402]  162.7 154.25 90 bottom
CV244  -  [C_0402]  197.56 154.37 90 top
CV245  -  [C_0402]  176.61 154.25 90 top
CV246  -  [C_0402]  175.72 154.25 90 top
CV247  -  [C_0402]  162.7 154.25 90 top
CV248  -  [C_0603]  174.07 154.32 90 bottom
CV249  -  [C_0603]  175.27 154.32 90 bottom
CV250  -  [C_0603]  183.15 154.39 90 bottom
CV251  -  [C_0603]  181.94 154.39 90 bottom
CV252  -  [C_0402]  163.59 154.25 90 top
CV253  -  [C_0402]  180.8 154.31 90 top
CV254  -  [C_0402]  181.69 154.31 90 top
CV255  -  [C_0402]  182.58 154.31 90 top
CV256  -  [C_0402]  196.67 154.37 90 top
CV257  -  [C_0402]  186.13 154.31 90 top
CV258  -  [C_0402]  194.01 154.37 90 top
CV259  -  [C_0402]  193.12 154.37 90 top
CV260  -  [C_0402]  163.59 154.25 90 bottom
CV261  -  [C_0402]  161.81 154.25 90 bottom
CV262  -  [C_0402]  160.92 154.25 90 top
CV263  -  [C_0402]  161.81 154.25 90 top
CV264  -  [C_0402]  164.48 154.25 90 top
CV265  -  [C_0402]  165.37 154.25 90 top
CV266  -  [C_0402]  166.26 154.25 90 top
CV267  -  [C_0402]  174.83 154.25 90 top
CV268  -  [C_0402]  172.16 154.25 90 top
CV269  -  [C_0402]  185.24 154.31 90 top
CV270  -  [C_0402]  195.78 154.37 90 top
CV271  -  [C_0402]  194.89 154.37 90 top
CV272  -  [C_0402]  218.07 131.96 90 top
CV273  -  [C_0402]  218.14 114.84 270 top
CV274  -  [C_0402]  203.16 133.75 180 top
CV275  -  [C_0402]  216.28 130.14 0 top
CV276  -  [C_0402]  203.16 130.19 180 bottom
CV277  -  [C_0402]  216.28 132 0 bottom
CV278  -  [C_0402]  216.41 116.67 0 bottom
CV279  -  [C_0402]  203.1 113.17 180 bottom
CV280  -  [C_0402]  203.1 115.9 180 top
CV281  -  [C_0402]  216.28 113.05 0 top
CV282  -  [C_0402]  216.28 140.42 0 bottom
CV283  -  [C_0402]  216.28 108.41 0 bottom
CV284  -  [C_0402]  216.28 107.52 0 bottom
CV285  -  [C_0402]  216.28 106.63 0 bottom
CV286  -  [C_0402]  216.28 105.74 0 bottom
CV287  -  [C_0402]  216.28 110.19 0 bottom
CV288  -  [C_0402]  216.3 137.74 0 bottom
CV289  -  [C_0402]  216.28 105.74 0 top
CV290  -  [C_0402]  216.3 136.85 0 bottom
CV291  -  [C_0402]  216.28 141.3 0 bottom
CV292  -  [C_0402]  216.28 142.19 0 bottom
CV293  -  [C_0402]  215.53 104.3 270 bottom
CV294  -  [C_0402]  216.42 104.3 270 bottom
CV295  -  [C_0603]  213.56 142.07 90 bottom
CV296  -  [C_0603]  214.83 142.07 90 bottom
CV297  -  [C_0603]  214.45 104.22 270 bottom
CV298  -  [C_0603]  213.25 104.22 270 bottom
CV299  -  [C_0402]  216.28 124.86 0 top
CV300  -  [C_0402]  216.28 139.53 0 bottom
CV301  -  [C_0402]  216.28 127.52 0 bottom
CV302  -  [C_0402]  216.28 135.08 0 bottom
CV303  -  [C_0402]  216.28 109.3 0 bottom
CV304  -  [C_0402]  216.28 131.08 0 bottom
CV305  -  [C_0402]  216.28 109.3 0 top
CV306  -  [C_0402]  216.28 108.41 0 top
CV307  -  [C_0402]  216.28 107.52 0 top
CV308  -  [C_0402]  216.28 123.91 0 top
CV310  -  [C_0402]  216.28 125.75 0 top
CV311  -  [C_0402]  216.28 126.64 0 top
CV312  -  [C_0402]  216.28 135.97 0 bottom
CV313  -  [C_0402]  216.28 128.41 0 bottom
CV314  -  [C_0402]  216.28 138.64 0 bottom
CV315  -  [C_0402]  216.28 129.3 0 bottom
CV316  -  [C_0402]  216.28 130.19 0 bottom
CV317  -  [C_0402]  216.28 106.63 0 top
CV318  -  [C_0402]  216.28 110.19 0 top
CV322  -  [C_0603]  183.99 117.88 270 top
CV323  -  [C_0603]  180.32 107.46 270 top
CV324  -  [C_0603]  177.77 125.43 90 top
CV325  -  [C_0402]  180.21 111.46 180 top
CV326  -  [C_0402]  161.82 109.68 270 bottom
CV327  -  [C_D2]  161.79 129.8 180 top
CV329  -  [C_0402]  167.29 98.07 90 top
CV331  -  [C_0402]  160.81 110.51 270 top
CV333  -  [C_0402]  159.41 111.62 90 top
CV335  -  [C_0402]  155.92 110.19 270 top
CX1  -  [C_0402]  216.7 173.75 180 top
CX2  -  [C_0402]  213.96 167.73 270 bottom
CX3  -  [C_0805]  215.01 167.9 0 bottom
CX4  -  [C_0402]  219.87 176.27 90 top
CX5  -  [C_0603]  224.5 175.72 90 top
CX6  -  [C_0402]  24.92 95.91 270 bottom
CX7  -  [C_0805]  216.21 172.41 180 top
CX8  -  [C_0805]  216.37 171.1 270 bottom
CX9  -  [C_0402]  217.83 166.84 270 top
CX10  -  [C_0402]  213.57 161.05 0 bottom
CX11  -  [C_0402]  213.2 170.37 90 bottom
CX12  -  [C_0402]  20.02 101.67 0 bottom
CX13  -  [C_0402]  20.02 100.79 0 bottom
CX14  -  [C_0402]  19.21 104.34 0 bottom
CX15  -  [C_0402]  19.21 103.45 0 bottom
CX16  -  [C_0402]  18.18 99.01 0 bottom
CX17  -  [C_0402]  18.18 98.12 0 bottom
CX18  -  [C_0402]  19.07 96.34 0 bottom
CX19  -  [C_0402]  19.07 95.45 0 bottom
CX20  -  [C_0402]  15.09 111.47 180 bottom
CX21  -  [C_0402]  14.13 107.4 270 bottom
CX22  -  [C_0603]  15.21 107.39 270 bottom
CX23  -  [C_0402]  15.01 101.66 90 bottom
CX24  -  [C_0402]  15.01 100.8 270 bottom
CX25  -  [C_0402]  14.13 104.33 90 bottom
CX26  -  [C_0402]  14.13 103.46 270 bottom
CX27  -  [C_0402]  13.11 99.06 90 bottom
CX28  -  [C_0402]  13.11 98.19 270 bottom
CX29  -  [C_0402]  14 96.39 90 bottom
CX30  -  [C_0402]  14 95.53 270 bottom
CX31  -  [C_0402]  199.04 170.9 180 bottom
CX32  -  [C_0402]  199.6 167.6 180 top
CX33  -  [C_0402]  199.04 170.03 180 bottom
CX34  -  [C_0402]  203.99 165.31 270 top
CX35  -  [C_0603]  198.09 168.98 180 bottom
CX36  -  [C_0805]  206.82 164.86 0 top
CX37  -  [C_0402]  204.88 175.58 90 top
CX38  -  [C_0402]  196.74 169.2 0 top
CX39  -  [C_0402]  196.74 168.31 0 top
CX40  -  [C_0402]  204.64 163.02 180 top
CX41  -  [C_0402]  205.77 165.31 270 top
CX42  -  [C_0402]  198.52 170.38 0 top
CX43  -  [C_0402]  198.52 171.27 0 top
CX44  -  [C_0402]  198.52 172.16 0 top
CX45  -  [C_0603]  204.56 161.81 180 top
CX46  -  [C_0402]  198.52 169.49 0 top
CX47  -  [C_0402]  199.33 161.78 180 top
CX48  -  [C_0805]  198.92 163.45 90 top
DA8  -  [BAT54C-7-F_SOT23-3]  38.13 25.32 0 top
DA10  -  [AZ5125-02SPR7G_SOT23-3]  18.13 11.19 90 top
DA12  -  [AZ5125-02SPR7G_SOT23-3]  16.44 14.46 0 top
DC1  -  [BAT54CW_SOT323-3]  203.31 13.16 180 bottom
DE1  -  [L03ESDL5V0CG3-2_SOT-523-3]  171.4 44.32 0 top
DH1  -  [RB751V-40_SOD323-2]  144.25 117.62 270 bottom
DI1  -  [IP4292CZ10-TBR_XSON10_2P5X1]  16.69 59.91 90 bottom
DI2  -  [L30ESDL5V0C3-2_SOT23-3]  17.09 57.03 90 bottom
DI4  -  [IP4292CZ10-TBR_XSON10_2P5X1]  17.51 46.76 90 bottom
DI5  -  [L30ESDL5V0C3-2_SOT23-3]  16.58 44.27 90 bottom
DI7  -  [L30ESDL5V0C3-2_SOT23-3]  15.04 27.89 90 bottom
DX1  -  [RB751V-40_SOD323-2]  219.42 165.64 270 bottom
FD1  -  [FIDUCIAL_C40M80]  227.46 160.12 180 bottom
FD2  -  [FIDUCIAL_C40M80]  18.82 18.24 180 bottom
FD3  -  [FIDUCIAL_C40M80]  28.35 35.13 0 top
FD4  -  [FIDUCIAL_C40M80]  227.42 177.37 0 top
FX1  -  [F_1206L150PR]  14.31 108.98 0 bottom
H2  -  [H_2P8]  109.2 13.4 0 top
H4  -  [H_2P8]  19.2 71.9 0 top
H5  -  [H_2P8]  21.9 4.9 0 top
H6  -  [H_3P3]  204.1 94.4 0 top
H7  -  [H_3P3]  153.3 144.5 0 top
H8  -  [H_2P8]  225.2 81.4 0 top
H9  -  [H_2P8]  225.2 168.4 0 top
H10  -  [H_3P3]  26.92 119.1 0 top
H11  -  [H_2P8]  164.2 185.4 0 top
H12  -  [H_2P8]  31.2 109.4 0 top
H16  -  [H_2P8]  127.6 154.8 0 top
H17  -  [H_2P8]  225.2 4.9 0 top
H18  -  [H_3P3]  19.2 38.1 0 top
H31  -  [H_3P7]  80.8 129.06 0 top
H32  -  [H_3P7]  141.2 103.66 0 top
H33  -  [H_3P7]  141.2 129.06 0 top
H34  -  [H_3P7]  80.8 103.66 0 top
H35  -  [H_3P7X3P2N]  195.55 187.5 0 top
J9  -  [JUMP_43X39]  185.84 86.5 180 bottom
J510  -  [JUMP_43X79]  100.59 31.57 180 bottom
J511  -  [JUMP_43X79]  92.63 31.57 0 bottom
J513  -  [JUMP_43X79]  139.79 27.23 270 top
JDB  -  [JESS_UCNR2210M008-0_8P]  210.6 45.7 270 top
JDIMM1  -  [LCN_DAN06-K4406-0102_204P]  41.8 71.4 0 bottom
JDIMM2  -  [LCN_DAN06-K4406-0102_204P]  120.35 71.44 0 bottom
JFAN  -  [ACES_85204-0300N_3P]  48.69 108.61 0 bottom
JHDD  -  [SANTA_193202-1_22P]  227.22 37.39 270 bottom
JHDMI  -  [LOTES_ABA-HDM-022-K01_19P]  8.08 99.15 270 bottom
JHP  -  [SINGA_2SJ3080-000111F_6P-T]  11.75 8.09 270 bottom
JKB  -  [HB_A823020-SBHR21_30P]  228.6 159.82 270 top
JLAN  -  [SANTA_130456-311_8P]  15 79.23 90 bottom
JLVDS  -  [STARC_107K40-000001-G2_40P]  204.45 173.45 0 bottom
JMINI  -  [CONCR_525B01BE17A_52P]  93.3 150.67 0 bottom
JODD  -  [SANTA_202801-1_13P]  227.05 98.22 270 bottom
JP3  -  [JUMP_43X39]  45.16 85.29 0 bottom
JP7  -  [JUMP_43X79]  220.21 115.83 0 bottom
JP8  -  [JUMP_43X39]  182.13 91.57 0 bottom
JP9  -  [JUMP_43X39]  214.01 151.26 0 bottom
JP12  -  [JUMP_43X39]  200.49 12.46 0 bottom
JP13  -  [JUMP_43X79]  219.31 60.09 270 top
JPWR  -  [HB_A090420-SAHR21_4P]  45.34 95.4 180 top
JREAD  -  [T-SOL_143-2300302602_22P_RV]  191.48 29.92 180 bottom
JRTC  -  [LOTES_AAA-BAT-054-K01_2P]  210.2 9.4 270 bottom
JSPK  -  [E-T_3703-Q04N-11R_4P]  69.77 21.88 90 top
JTOUCH  -  [ACES_88460-00601-P01_6P]  23.71 96.89 180 top
JTP  -  [PS_HPF10052-06M000R_6P]  66.35 110.35 0 top
JUSB1  -  [ACON_TARA4-9K1311_9P]  12.69 67.1 90 bottom
JUSB2  -  [ACON_TARA4-9K1311_9P]  12.69 49.5 90 bottom
JUSB3  -  [ACON_UARBG-4K1926_4P]  10.32 31.9 90 bottom
JXDP1  -  [SAMTE_BSH-030-01-L-D-A_60P]  73.2 93.43 180 bottom
L1  -  [MURAT_LQM2MPN2R2NG0L_2P]  119.54 137.4 270 bottom
L2  -  [MURAT_LQM2MPN2R2NG0L_2P]  121.02 141.62 0 bottom
L3  -  [MURAT_LQM2MPN2R2NG0L_2P]  123.88 138.89 0 bottom
L4  -  [MURAT_LQM2MPN2R2NG0L_2P]  121.76 139.88 270 bottom
L5  -  [MURAT_LQM2MPN2R2NG0L_2P]  117.31 137.4 270 bottom
LA1  -  [MURAT_BLM15BB221SN1D_2P]  32.29 19.12 0 top
LA3  -  [R_0603]  64.04 20.71 0 top
LA4  -  [R_0603]  64.04 21.92 0 top
LA5  -  [R_0603]  63.08 23.7 0 top
LA6  -  [R_0603]  63.08 24.9 0 top
LA7  -  [KC_FBMA-L10-160808-800LMT_2P]  15.59 20.28 90 top
LA8  -  [KC_FBMA-L10-160808-800LMT_2P]  23.41 11.1 0 top
LA9  -  [KC_FBMA-L10-160808-800LMT_2P]  23.41 12.62 0 top
LA10  -  [KC_FBMA-L10-160808-800LMT_2P]  17.11 20.28 90 top
LE1  -  [KC_FBMA-L11-160808-800LMT_2P]  199.62 35.7 0 top
LE2  -  [KC_FBMA-L11-160808-800LMT_2P]  194.21 55.5 270 top
LED1  -  [LED_12-21C-T3D-CM2P1B18X-2C_3P]  31.81 10.74 0 top
LED2  -  [LED_12-21C-T3D-CM2P1B18X-2C_3P]  40.8 10.74 0 top
LED3  -  [LED_HT-210UD5-BP5_3P]  46.9 10.74 0 top
LED4  -  [LED_12-21C-T3D-CM2P1B18X-2C_3P]  58.81 10.7 0 top
LI1  -  [MURAT_DLW21SN670HQ2L_4P]  21.26 59.49 180 bottom
LI2  -  [KC_WCM-2012HS-900T_4P]  22.85 57.43 180 bottom
LI3  -  [MURAT_DLW21SN670HQ2L_4P]  21.26 61.4 180 bottom
LI4  -  [MURAT_DLW21SN670HQ2L_4P]  22.34 46.16 180 bottom
LI5  -  [KC_WCM-2012HS-900T_4P]  22.85 44.61 180 bottom
LI6  -  [MURAT_DLW21SN670HQ2L_4P]  22.34 47.93 180 bottom
LI7  -  [KC_WCM-2012HS-900T_4P]  20.75 27.91 180 bottom
LI10  -  [KC_WCM-2012HS-900T_4P]  205.68 49.12 0 top
LR2  -  [KC_WCM-2012HS-900T_4P]  171.95 33.05 180 bottom
LV12  -  [R_0402]  162.59 112.64 270 top
LV13  -  [R_0402]  162.59 115.14 270 top
LV14  -  [R_0402]  160.55 106.19 270 bottom
LV15  -  [R_0402]  160.55 103.84 270 bottom
LV16  -  [R_0402]  159.54 105.27 90 bottom
LV17  -  [CHENG_MBK1608121YZF_2P]  153.38 111.28 90 top
LV18  -  [CHENG_MBK1608121YZF_2P]  156.77 114.75 0 bottom
LV19  -  [R_0402]  169.05 96.73 0 bottom
LV20  -  [R_0402]  184.1 99.51 0 bottom
LV21  -  [KC_FBMA-L11-160808-800LMT_2P]  204.47 148.23 180 top
LV22  -  [R_0402]  191.75 94.75 180 bottom
LV23  -  [KC_FBMA-L11-160808-800LMT_2P]  194.21 92.92 90 bottom
LV25  -  [R_0402]  180.95 113.1 180 top
LV26  -  [R_0402]  182.28 114.68 180 top
LX1  -  [KC_FBMA-L11-201209-221LMA30_2P]  214.6 169.43 90 bottom
LX2  -  [KC_WCM-2012HS-900T_4P]  17.83 101.63 180 bottom
LX3  -  [KC_WCM-2012HS-900T_4P]  16.94 104.3 180 bottom
LX4  -  [KC_WCM-2012HS-900T_4P]  15.93 99.03 180 bottom
LX5  -  [KC_WCM-2012HS-900T_4P]  16.82 96.3 180 bottom
LX6  -  [KC_WCM-2012HS-900T_4P]  219.02 165.34 90 top
LX7  -  [KC_FBMA-L11-201209-221LMA30_2P]  205.96 162.89 270 top
LX8  -  [KC_FBMA-L11-201209-221LMA30_2P]  197.49 167.19 0 bottom
LX9  -  [CYNTE_PG031B-4R7MS_2P]  200.48 164.09 0 top
ME1  -  [SHORTPADS]  115.46 40.16 180 bottom
NOREF  -  []  80.8 129.06 0 top
NOREF#2  -  []  38.32 50.56 0 top
NOREF#3  -  []  26.92 119.1 0 top
NOREF#4  -  []  19.2 71.9 0 top
NOREF#5  -  []  123.09 42 0 top
NOREF#6  -  []  225.2 168.4 0 top
NOREF#7  -  []  127.6 154.8 0 top
NOREF#8  -  []  127.96 79.22 0 top
NOREF#9  -  []  31.2 109.4 0 top
NOREF#10  -  []  225.2 81.4 0 top
NOREF#11  -  []  19.2 38.1 0 top
NOREF#12  -  []  141.2 129.05 0 top
NOREF#13  -  []  108.36 -20.5 0 top
NOREF#14  -  []  141.2 103.65 0 top
NOREF#15  -  []  204.1 94.4 0 top
NOREF#16  -  []  80.8 103.66 0 top
NOREF#17  -  []  74.32 49.5 0 top
NOREF#18  -  []  21.9 4.9 0 top
NOREF#19  -  []  225.2 4.9 0 top
NOREF#20  -  []  164.2 185.4 0 top
NOREF#21  -  []  32.86 216.61 0 top
NOREF#22  -  []  109.2 13.4 0 top
NOREF#23  -  []  104.11 81.61 0 top
NOREF#24  -  []  153.3 144.5 0 top
NOREF#25  -  []  50.45 30.36 0 top
NOREF#26  -  []  69.88 31.6 180 bottom
NOREF#27  -  []  158.78 39.19 180 bottom
NOREF#28  -  []  137.89 89.16 180 bottom
NOREF#29  -  []  140.94 37.03 180 bottom
PBATT  -  [SUYIN_200028MR009G502ZL_9P]  139.52 188.7 0 bottom
PC1  -  [C_0402]  139.79 179.89 90 bottom
PC2  -  [C_0402]  140.68 179.89 90 bottom
PC3  -  [C_0402]  138.71 168.49 270 top
PC4  -  [C_0402]  137.82 168.49 270 top
PC5  -  [C_0402]  129.54 171.91 180 top
PC7  -  [C_0402]  158.07 181.05 0 bottom
PC8  -  [C_0402]  158.07 182.19 0 bottom
PC13  -  [C_0402]  130.85 180.8 180 top
PC14  -  [C_0402]  132.11 164.49 270 top
PC15  -  [C_0402]  127.54 163.57 90 top
PC16  -  [C_0402]  127.47 167.32 90 top
PC100  -  [C_0603]  119 13.19 90 top
PC101  -  [C_MP6VLPS220MC4R2]  137.7 18.26 0 bottom
PC102  -  [C_0402]  129.82 12.06 90 top
PC103  -  [C_0603]  132.68 21.25 180 top
PC104  -  [C_0402]  131.52 15.79 0 top
PC105  -  [C_0603]  128.54 18.07 180 bottom
PC106  -  [C_0603]  127.58 20.18 180 bottom
PC107  -  [C_MP6VLPS220MC4R2]  117.94 18.43 180 bottom
PC108  -  [C_0402]  126.67 12.99 270 bottom
PC109  -  [C_0603]  127.82 12.92 270 top
PC110  -  [C_0402]  123.21 16.39 0 top
PC111  -  [C_0603]  121.63 21.46 0 top
PC112  -  [C_0805]  128.58 25.41 270 bottom
PC113  -  [C_0402]  126.33 25.55 270 top
PC114  -  [C_0402]  127.23 25.58 270 top
PC115  -  [C_0805]  128.58 25.41 270 top
PC200  -  [C_0603]  154.91 21.68 0 bottom
PC201  -  [C_0402]  163.8 14.95 270 bottom
PC202  -  [C_0402]  162 24.33 0 bottom
PC203  -  [C_0402]  162 26.11 0 bottom
PC204  -  [C_0603]  159.67 20.03 90 bottom
PC205  -  [C_0805]  154.91 27.14 270 bottom
PC206  -  [C_0805]  159.86 16.36 270 bottom
PC207  -  [C_0402]  156.42 11.19 0 bottom
PC208  -  [C_0402]  162.91 14.95 270 bottom
PC209  -  [C_0603]  160.88 21.42 270 bottom
PC210  -  [C_0402]  159.67 28.22 90 bottom
PC211  -  [C_0805]  156.88 28.6 0 bottom
PC212  -  [C_0805]  161.57 16.36 270 bottom
PC213  -  [C_MP6VU330MC6]  146.34 22.44 0 bottom
PC300  -  [C_0402]  148.17 150.12 0 bottom
PC301  -  [C_0603]  139.23 150.5 90 bottom
PC302  -  [C_0603]  148.43 158.05 180 bottom
PC303  -  [C_0402]  143.42 157.28 90 bottom
PC304  -  [C_0402]  142.53 157.28 90 bottom
PC305  -  [C_0805]  141.32 155.16 270 bottom
PC306  -  [C_0805]  139.61 155.16 270 bottom
PC307  -  [C_0402]  147.74 153.72 90 bottom
PC308  -  [C_0805]  141.7 142.35 90 top
PC309  -  [C_0805]  143.41 142.35 90 top
PC310  -  [C_0805]  146.84 142.35 90 top
PC311  -  [C_0805]  145.13 142.35 90 top
PC312  -  [C_0603]  147.04 155.64 0 bottom
PC313  -  [C_0603]  144.5 157.48 0 bottom
PC400  -  [C_0805]  112.85 29.6 270 bottom
PC401  -  [C_0402]  107.44 25.89 0 bottom
PC402  -  [C_0805]  111.14 29.6 270 bottom
PC403  -  [C_0402]  111.9 26.85 270 bottom
PC404  -  [C_0402]  113.68 24.69 270 bottom
PC405  -  [C_0805]  107.9 23.13 90 bottom
PC501  -  [C_0402]  117.61 138.97 180 bottom
PC502  -  [C_0402]  114.24 145.06 270 bottom
PC503  -  [C_0603]  82.9 135.39 90 bottom
PC504  -  [C_0402]  86.95 136.35 0 top
PC505  -  [C_0603]  90.14 131.66 0 bottom
PC506  -  [C_0402]  88.74 136.29 270 top
PC507  -  [C_0402]  89.94 135.38 90 top
PC508  -  [C_0603]  89.69 142.7 270 bottom
PC509  -  [C_0402]  90.26 139.85 270 top
PC510  -  [C_0402]  93.89 139.08 180 bottom
PC511  -  [C_0402]  93.89 139.96 180 bottom
PC512  -  [C_0402]  86.95 135.46 0 top
PC513  -  [C_0402]  92.66 134.38 0 bottom
PC514  -  [C_0402]  91.79 132.66 90 bottom
PC515  -  [C_EEEFZ1E101P]  129.63 143.23 270 bottom
PC516  -  [C_EEEFZ1E101P]  136.74 143.16 270 bottom
PC517  -  [C_0805]  117.31 143.24 90 top
PC518  -  [C_0805]  117.31 143.24 90 bottom
PC519  -  [C_0402]  115.13 144.14 90 bottom
PC520  -  [C_0402]  107.22 142.81 90 top
PC521  -  [C_0402]  116.02 144.14 90 bottom
PC522  -  [C_0402]  85.46 139.9 180 bottom
PC523  -  [C_0402]  83.15 135.15 90 top
PC600  -  [C_0805]  217.87 98.25 0 top
PC601  -  [C_0402]  216.61 92.66 0 bottom
PC602  -  [C_0805]  217.87 96.21 0 top
PC603  -  [C_0402]  220.06 93.37 270 top
PC604  -  [C_0402]  222.16 88.02 180 bottom
PC605  -  [C_0805]  217.14 89.96 90 bottom
PC701  -  [C_0603]  143.03 169.17 270 bottom
PC702  -  [C_0402]  143.81 166.63 180 bottom
PC703  -  [C_0805]  157.7 166.24 0 top
PC704  -  [C_0805]  157.7 164.46 0 top
PC705  -  [C_0402]  158 168.86 0 top
PC706  -  [C_0603]  157.83 167.78 0 top
PC707  -  [C_0603]  167.41 167.65 0 bottom
PC708  -  [C_0402]  166.4 167.46 90 bottom
PC709  -  [C_0603]  164.68 172.54 180 top
PC710  -  [C_0603]  163.92 167.08 180 top
PC711  -  [C_0402]  172.25 168.1 180 top
PC712  -  [C_0805]  146.63 179.72 0 top
PC713  -  [C_0805]  146.63 181.43 0 top
PC714  -  [C_0805]  145.93 175.97 0 top
PC715  -  [C_0402]  154.13 176.5 0 top
PC716  -  [C_0805]  146.63 183.14 0 top
PC717  -  [C_0402]  167.75 165.94 180 top
PC718  -  [C_0805]  145.93 174.25 0 top
PC719  -  [C_0402]  169.64 174.06 270 top
PC720  -  [C_0402]  195.61 51.71 270 bottom
PC721  -  [C_0603]  162.53 168.35 0 top
PC722  -  [C_0402]  167.73 175.14 0 top
PC723  -  [C_0402]  171.99 177.11 180 top
PC724  -  [C_EEEFZ1E101P]  157.1 164.03 0 bottom
PC803  -  [C_0603]  207.1 61.73 90 bottom
PC804  -  [C_0805]  212.73 71.83 0 top
PC805  -  [C_0805]  212.73 69.54 0 top
PC806  -  [C_0402]  204.23 51.95 0 bottom
PC807  -  [C_0603]  202.47 61.67 0 bottom
PC808  -  [C_0805]  212.73 67.26 0 top
PC809  -  [C_0402]  201.51 54.63 270 bottom
PC810  -  [C_0603]  201.51 57.48 180 top
PC811  -  [C_0603]  205.32 58.94 0 top
PC813  -  [C_0402]  205.32 55.27 270 top
PC814  -  [C_0402]  204.23 51.06 0 bottom
PC815  -  [C_0603]  208.56 62.81 0 top
PC816  -  [C_0402]  201.58 55.5 90 top
PC817  -  [C_0402]  201.58 51.05 90 bottom
PC818  -  [C_0402]  206.04 53.73 180 bottom
PC819  -  [C_0402]  199.11 59.26 180 bottom
PC820  -  [C_0402]  199.11 58.37 180 bottom
PC821  -  [C_0402]  201.59 54.62 180 top
PC831  -  [C_0402]  213.38 74.05 0 top
PC832  -  [C_0402]  213.38 73.16 0 top
PC835  -  [C_0603]  194.53 89.16 90 top
PC836  -  [C_D1]  204.04 84.58 0 top
PC837  -  [C_D1]  200.82 86.26 270 bottom
PC838  -  [C_D1]  195.99 84.68 270 bottom
PC839  -  [C_D1]  191.23 84.68 270 bottom
PC840  -  [C_0402]  181.44 122.2 0 top
PC841  -  [C_0402]  181.5 117.69 0 top
PC842  -  [C_0402]  182.08 118.93 90 top
PC843  -  [C_0402]  179.54 117.69 0 top
PC844  -  [C_0402]  177.34 117.24 180 top
PC845  -  [C_0402]  177.34 118.7 180 top
PC846  -  [C_0402]  176.49 120.67 0 top
PC847  -  [C_0402]  179.59 115.96 0 top
PC848  -  [C_0402]  181.37 115.96 0 top
PC849  -  [C_0402]  173.88 102.2 270 bottom
PC850  -  [C_0402]  178.21 119.85 270 top
PC851  -  [C_0402]  179.09 119.45 0 top
PC852  -  [C_0402]  178.73 115.71 180 top
PC853  -  [C_0402]  175.43 120.67 180 top
PC854  -  [C_0402]  174.46 117.24 0 top
PC855  -  [C_0402]  175.43 122.13 180 top
PC856  -  [C_0402]  179.28 122.2 0 top
PC857  -  [C_0402]  179.34 123.66 0 top
PC858  -  [C_0402]  181.44 123.66 0 top
PC859  -  [C_0402]  179.28 120.74 0 top
PC860  -  [C_0402]  181.44 120.74 0 top
PC861  -  [C_0402]  176.95 115.71 180 top
PC862  -  [C_0402]  178.2 112.47 0 top
PC863  -  [C_0402]  175.17 115.71 180 top
PC864  -  [C_0402]  176.36 122.13 0 top
PC865  -  [C_0402]  176.49 123.63 0 top
PC866  -  [C_0402]  174.46 118.7 0 top
PC867  -  [C_0603]  192.81 89.16 90 top
PC868  -  [C_0603]  196.31 89.16 90 top
PC869  -  [C_0402]  207.62 56.21 180 top
PC870  -  [C_0603]  198.02 89.16 90 top
PC871  -  [C_0402]  173.58 117.55 90 top
PC872  -  [C_0402]  172.18 117.02 90 top
PC873  -  [C_0402]  172.18 119.73 270 top
PC901  -  [C_0805]  97.44 122.73 90 top
PC902  -  [C_0805]  100.3 122.67 90 top
PC903  -  [C_0805]  102.77 122.67 90 top
PC904  -  [C_0805]  105.31 122.67 90 top
PC905  -  [C_0805]  107.79 122.67 90 top
PC906  -  [C_0805]  110.33 122.67 90 top
PC907  -  [C_0805]  112.8 122.67 90 top
PC908  -  [C_0805]  96.93 117.9 90 top
PC909  -  [C_0805]  100.65 137.55 0 top
PC910  -  [C_0805]  96.87 114.79 90 top
PC911  -  [C_0805]  97.35 135.33 0 top
PC912  -  [C_0805]  110.81 135.33 0 top
PC913  -  [C_0805]  110.75 137.49 0 top
PC914  -  [C_0805]  107.45 135.33 0 top
PC915  -  [C_0805]  107.38 137.49 0 top
PC916  -  [C_0805]  104.08 135.33 0 top
PC917  -  [C_0805]  100.71 135.33 0 top
PC918  -  [C_0805]  110.81 133.93 0 bottom
PC919  -  [C_0805]  107.45 133.93 0 bottom
PC920  -  [C_0805]  104.08 133.93 0 bottom
PC921  -  [C_0805]  100.71 133.93 0 bottom
PC922  -  [C_0805]  103.95 137.55 0 top
PC923  -  [C_0805]  97.35 133.93 0 bottom
PC1100  -  [C_0402]  178.64 173.37 0 top
PC1101  -  [C_0402]  178.64 174.25 0 top
PC1102  -  [C_0805]  178.82 175.59 0 top
PC1103  -  [C_0603]  183.16 170.25 90 top
PC1104  -  [C_0402]  188.19 172.03 180 bottom
PC1105  -  [C_0603]  183.67 173.05 90 top
PC1106  -  [C_0402]  181.45 170.11 90 top
PC1108  -  [C_MP6VU330MC6]  182.65 167.14 0 bottom
PC1200  -  [C_0402]  183.99 186.18 90 bottom
PC1201  -  [C_0805]  190.85 185.34 90 bottom
PC1202  -  [C_0805]  177.8 177.49 0 bottom
PC1203  -  [C_0402]  175.88 182.71 180 bottom
PC1204  -  [C_0805]  177.8 179.21 0 bottom
PC1205  -  [C_0603]  176.37 183.78 180 bottom
PC1206  -  [C_0805]  189.07 185.34 90 bottom
PC1207  -  [C_0805]  189.07 177.01 270 bottom
PC1209  -  [C_0402]  175.88 181.82 180 bottom
PC1210  -  [C_0603]  175.81 186.52 270 bottom
PC1211  -  [C_0805]  190.78 177.01 270 bottom
PC1212  -  [C_0603]  181.13 176.16 90 bottom
PC1213  -  [C_0603]  178.22 185.12 90 bottom
PC1214  -  [C_0402]  173.46 184.16 180 bottom
PC1300  -  [C_0805]  199.1 73.38 270 top
PC1301  -  [C_0805]  195 60.72 180 bottom
PC1302  -  [C_0402]  194.67 62.62 180 top
PC1303  -  [C_0805]  193.64 73.38 270 top
PC1304  -  [C_0402]  197.15 65.03 180 top
PC1305  -  [C_0805]  197.32 73.38 270 top
PC1306  -  [C_0402]  197.77 63.52 270 top
PC1307  -  [C_0402]  196.94 65.11 270 bottom
PC1308  -  [C_0805]  195.55 73.38 270 top
PD1  -  [IP4223CZ6_SO6]  142.24 185.05 270 bottom
PD2  -  [TVNST52302AB0_SOT523-3]  139.74 181.94 180 top
PD3  -  [TVNST52302AB0_SOT523-3]  144.11 185.24 270 bottom
PD101  -  [L03ESDL5V0CG3-2_SOT-523-3]  122.63 13.98 90 top
PD701  -  [RB751V-40_SOD323-2]  162.53 171.02 0 top
PH1  -  [R_0402]  106.19 113.74 0 top
PH501  -  [R_0402]  95.58 143.46 0 bottom
PH502  -  [R_0402]  111.93 144.16 180 bottom
PH800  -  [R_0402]  203.86 79.08 270 bottom
PJP100  -  [JUMP_43X118]  134.78 13.39 270 bottom
PJP101  -  [JUMP_43X118]  122.58 13.51 270 bottom
